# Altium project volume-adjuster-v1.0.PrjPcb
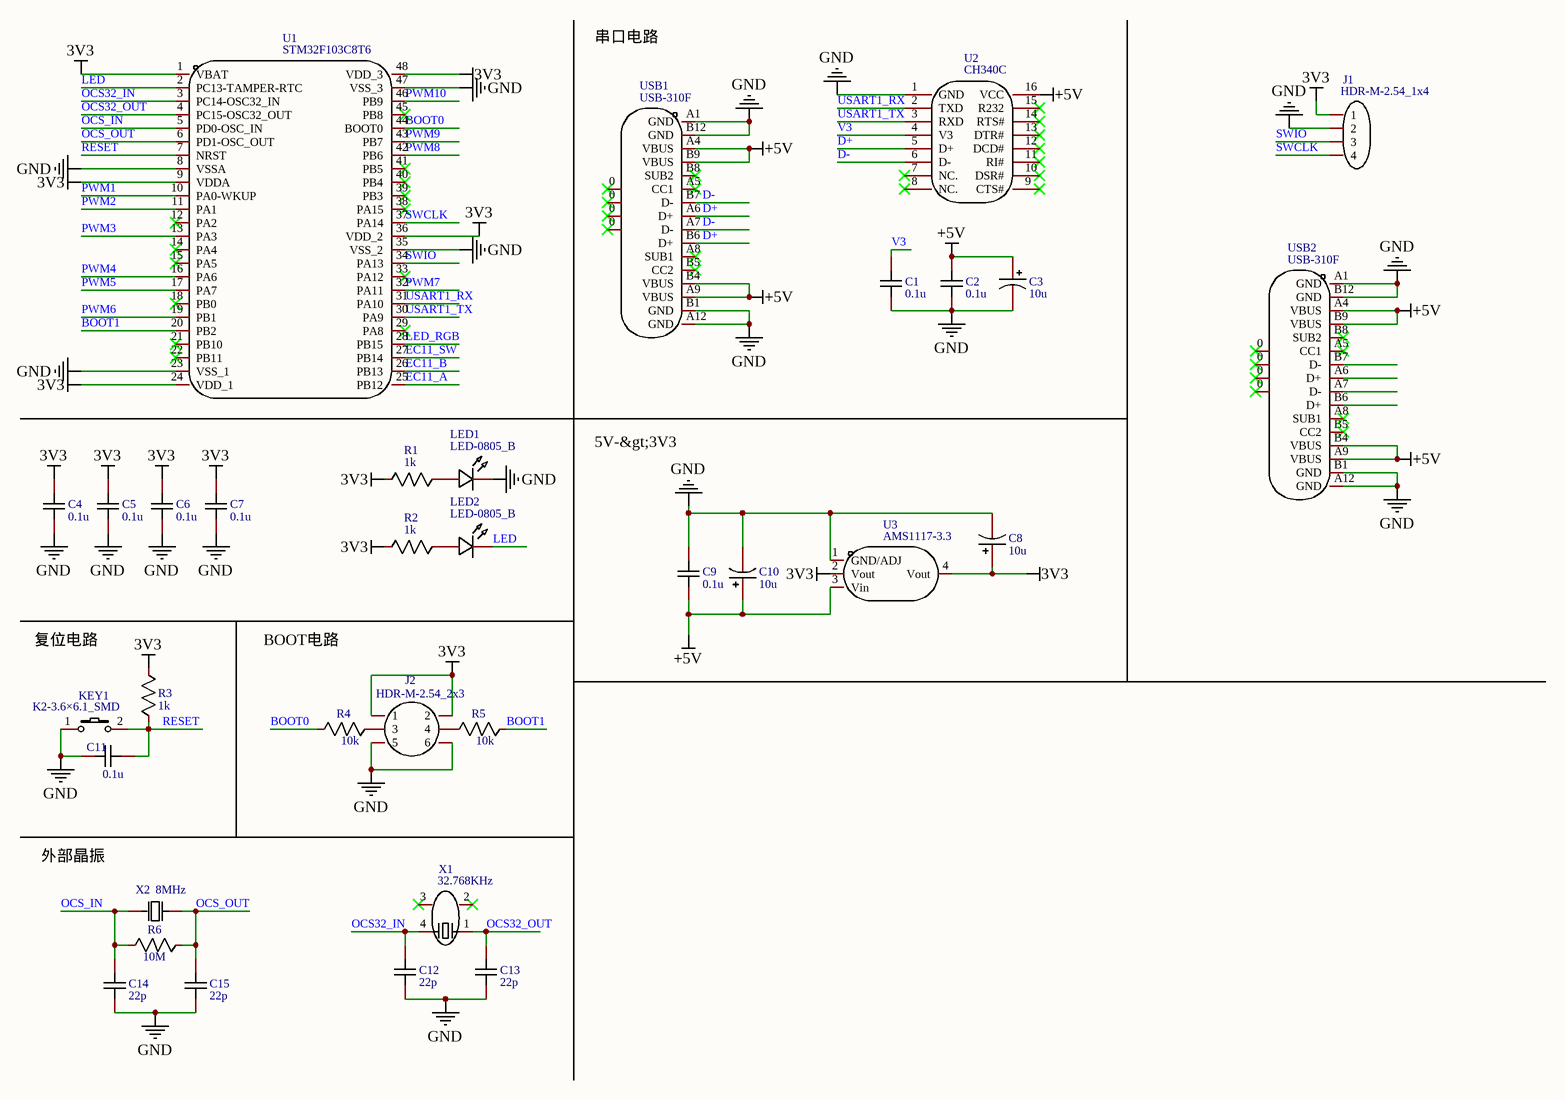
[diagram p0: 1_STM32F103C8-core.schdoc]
2 sheets, 59 parts. Net scope: global (net labels, ports and power ports of the same name join across sheets).
Board file: PCB_volume-adjuster.pcbdoc
Sheets:
  1_STM32F103C8-core.schdoc
  2_外围电路.schdoc

## Sheet 1_STM32F103C8-core.schdoc
size 497 x 243 mm; Name: A_A4; Symbol: A_A4; Device: A_A4; @Project Name: volume-adjuster-v1.0; REV: 1.0; Date: 2023-04-22; Sheet: 1/1; Draw By: wfei &amp; zzc; Company: 眼镜蛇小队; Convert to PCB: yes; Add into BOM: yes; SheetNumber: 1; SheetTotal: 2

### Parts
C1  0.1u  [C0805]
C2  0.1u  [C0805]
C3  10u  [CASE-A_3216]
C4  0.1u  [C0805]
C5  0.1u  [C0805]
C6  0.1u  [C0805]
C7  0.1u  [C0805]
C8  10u  [CASE-A_3216]
C9  0.1u  [C0805]
C10  10u  [CASE-A_3216]
C11  0.1u  [C0805]
C12  22p  [C0805]
C13  22p  [C0805]
C14  22p  [C0805]
C15  22p  [C0805]
J1  HDR-M-2.54_1x4  [HDR-M-2.54_1X4]
J2  HDR-M-2.54_2x3  [HDR-M-2.54_2X3]
KEY1  K2-3.6×6.1_SMD  [KEY-SMD_2P-L6.2-W3.6-LS8.0]
LED1  LED-0805_B  [LED0805_BLUE]
LED2  LED-0805_B  [LED0805_BLUE]
R1  1k  [R0805]
R2  1k  [R0805]
R3  1k  [R0805]
R4  10k  [R0805]
R5  10k  [R0805]
R6  10M  [R0805]
U1  STM32F103C8T6  [LQFP-48_L7.0-W7.0-P0.50-LS9.0-BL]
U2  CH340C  [SOP-16_L10.0-W3.9-P1.27-LS6.0-BL]
U3  AMS1117-3.3  [SOT-223-3_L6.5-W3.4-P2.30-LS7.0-BR]
USB1  USB-310F  [USB-C-SMD_20P-P0.50-L6.5-W8.9]
USB2  USB-310F  [USB-C-SMD_20P-P0.50-L6.5-W8.9]
X1  32.768KHz  [MC-306_4P-L8.0-W3.2-P5.5-BL]
X2  8MHz  [OSC-TH_L11.1-W4.7-P4.88]

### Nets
3V3: C4.2 C5.2 C6.2 C7.2 C8.1 J1.1 J2.1 J2.2 R1.1 R2.1 R3.2 U1.1(VBAT) U1.9(VDDA) U1.24(VDD_1) U1.36(VDD_2) U1.48(VDD_3) U3.2(Vout) U3.4(Vout)
+5V: C2.2 C3.1 C9.1 C10.1 U2.16(VCC) U3.3(Vin) USB1.A4(VBUS) USB1.A9(VBUS) USB1.B4(VBUS) USB1.B9(VBUS) USB2.A4(VBUS) USB2.A9(VBUS) USB2.B4(VBUS) USB2.B9(VBUS)
GND: C1.1 C2.1 C3.2 C4.1 C5.1 C6.1 C7.1 C8.2 C9.2 C10.2 C11.2 C12.1 C13.1 C14.1 C15.1 J1.2 J2.5 J2.6 KEY1.1 LED1.2 U1.8(VSSA) U1.23(VSS_1) U1.35(VSS_2) U1.47(VSS_3) U2.1(GND) U3.1(GND/ADJ) USB1.A1(GND) USB1.A12(GND) USB1.B1(GND) USB1.B12(GND) USB2.A1(GND) USB2.A12(GND) USB2.B1(GND) USB2.B12(GND)
BOOT0: R4.1 U1.44(BOOT0)
BOOT1: R5.2 U1.20(PB2)
D+: U2.5(D+) USB1.A6(D+) USB1.B6(D+)
D-: U2.6(D-) USB1.A7(D-) USB1.B7(D-)
EC11_A: U1.25(PB12)
EC11_B: U1.26(PB13)
EC11_SW: U1.27(PB14)
LED: LED2.2 U1.2(PC13-TAMPER-RTC)
LED_RGB: U1.28(PB15)
OCS32_IN: C12.2 U1.3(PC14-OSC32_IN) X1.4
OCS32_OUT: C13.2 U1.4(PC15-OSC32_OUT) X1.1
OCS_IN: C14.2 R6.1 U1.5(PD0-OSC_IN) X2.1(OSC1)
OCS_OUT: C15.2 R6.2 U1.6(PD1-OSC_OUT) X2.2(OSC2)
PWM1: U1.10(PA0-WKUP)
PWM2: U1.11(PA1)
PWM3: U1.13(PA3)
PWM4: U1.16(PA6)
PWM5: U1.17(PA7)
PWM6: U1.19(PB1)
PWM7: U1.32(PA11)
PWM8: U1.42(PB6)
PWM9: U1.43(PB7)
PWM10: U1.46(PB9)
RESET: C11.1 KEY1.2 R3.1 U1.7(NRST)
SWCLK: J1.4 U1.37(PA14)
SWIO: J1.3 U1.34(PA13)
USART1_RX: U1.31(PA10) U2.2(TXD)
USART1_TX: U1.30(PA9) U2.3(RXD)
V3: C1.2 U2.4(V3)
NetJ2_3: J2.3 R4.2
NetJ2_4: J2.4 R5.1
NetLED1_1: LED1.1 R1.2
NetLED2_1: LED2.1 R2.2

Not connected (* = marked no-connect by the designer): U1 12(PA2)* 14(PA4)* 15(PA5)* 18(PB0)* 21(PB10)* 22(PB11)* 29(PA8)* 33(PA12)* 38(PA15)* 39(PB3)* 40(PB4)* 41(PB5)* 45(PB8)*; U2 7(NC.)* 8(NC.)* 9(CTS#)* 10(DSR#)* 11(RI#)* 12(DCD#)* 13(DTR#)* 14(RTS#)* 15(R232)*; USB1 0* A5(CC1)* A8(SUB1)* B5(CC2)* B8(SUB2)*; USB2 0* A5(CC1)* A6(D+) A7(D-) A8(SUB1)* B5(CC2)* B6(D+) B7(D-) B8(SUB2)*; X1 2* 3*

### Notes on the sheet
- 串口电路
- 5V-&gt;3V3
- 复位电路
- BOOT电路
- 外部晶振

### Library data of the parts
C1 C2 C4-C7 C9 C11 = 0.1u: Convert to PCB: yes
C3 C8 C10 = 10u: Convert to PCB: yes
C12-C15 = 22p: Convert to PCB: yes
J1 = HDR-M-2.54_1x4: Convert to PCB: yes
J2 = HDR-M-2.54_2x3: Convert to PCB: yes
KEY1 = K2-1107ST-A4SW-06: 制造商: 韩国韩荣; Convert to PCB: yes
LED1 LED2 = D-B080508B1-KS2: Manufacturer: 方舟 ARKLED; Convert to PCB: yes
R1-R3 = 1k: Convert to PCB: yes
R4 R5 = 10k: Convert to PCB: yes
R6 = 10M: Convert to PCB: yes
U1 = STM32F103C8T6: Manufacturer: STMicroelectronics; Convert to PCB: yes
U2 = CH340C: Manufacturer: WCH; Convert to PCB: yes
U3 = AMS1117-3.3: Manufacturer: AMS; Convert to PCB: yes
USB1 USB2 = USB-310F: Manufacturer: HOOYA; Convert to PCB: yes
X1 = Q13MC3061000300: Manufacturer: EPSON; Convert to PCB: yes
X2 = S1C80000VWGAC: 频率:8MHz;频率公差:±20ppm;频率稳定度:±30ppm;负载电容:16pF;; Manufacturer: JYJE(晶友嘉); Add into BOM: yes; Crystal Type: 直插无源晶振; Frequency Tolerance: ±20ppm; Frequency Stability: ±30ppm; Load Capacitance: 16pF; Equivalent Series Resistance (ESR): 60Ω

## Sheet 2_外围电路.schdoc
size 497 x 243 mm; Name: A_A4; Symbol: A_A4; Device: A_A4; @Project Name: volume-adjuster-v1.0; REV: 1.0; Date: 2023-04-22; Sheet: 1/1; Draw By: wfei &amp; zzc; Company: Your Company; Convert to PCB: yes; Add into BOM: yes; SheetNumber: 2; SheetTotal: 2
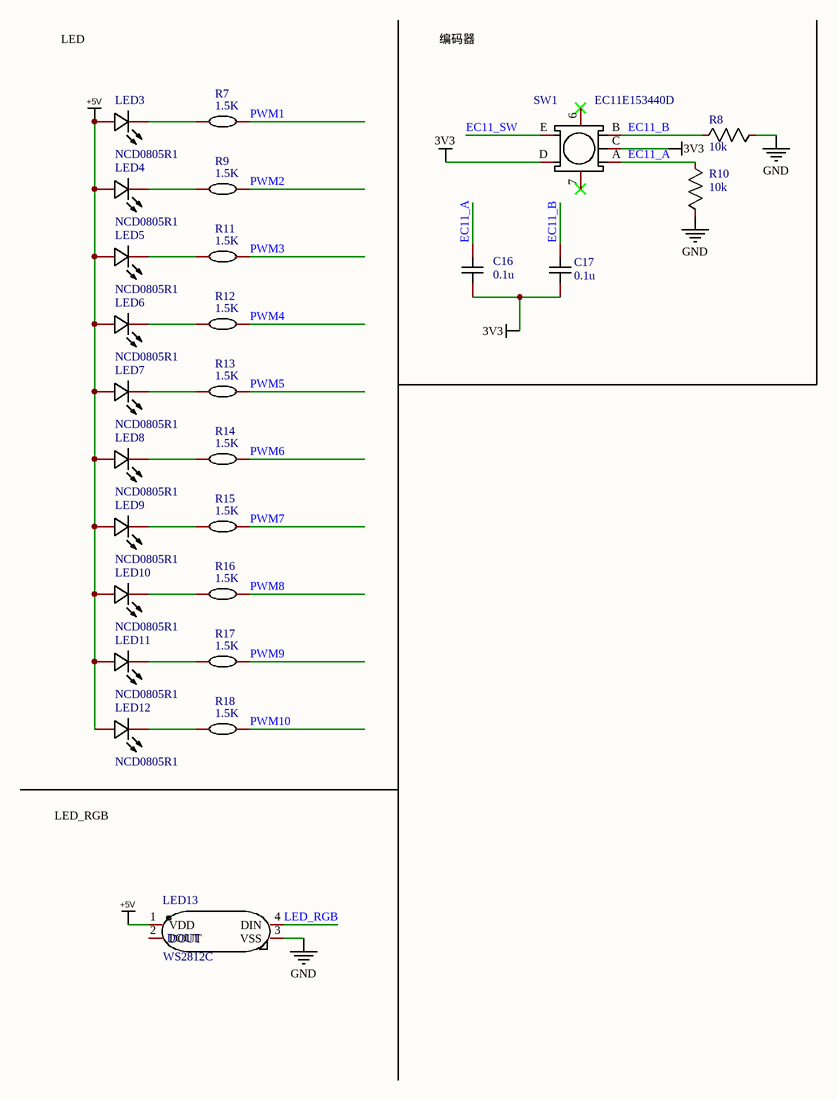
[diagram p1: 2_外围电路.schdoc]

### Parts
C16  0.1u  [C0805]
C17  0.1u  [C0805]
LED3  NCD0805R1  [LED0805-RD_RED]
LED4  NCD0805R1  [LED0805-RD_RED]
LED5  NCD0805R1  [LED0805-RD_RED]
LED6  NCD0805R1  [LED0805-RD_RED]
LED7  NCD0805R1  [LED0805-RD_RED]
LED8  NCD0805R1  [LED0805-RD_RED]
LED9  NCD0805R1  [LED0805-RD_RED]
LED10  NCD0805R1  [LED0805-RD_RED]
LED11  NCD0805R1  [LED0805-RD_RED]
LED12  NCD0805R1  [LED0805-RD_RED]
LED13  NAME: DOUT  [LED-SMD_4P-L5.0-W5.0-LS5.4-TL-1]  (hidden comment: WS2812C)
R7  1.5K  [R0805]
R8  10k  [R0805]
R9  1.5K  [R0805]
R10  10k  [R0805]
R11  1.5K  [R0805]
R12  1.5K  [R0805]
R13  1.5K  [R0805]
R14  1.5K  [R0805]
R15  1.5K  [R0805]
R16  1.5K  [R0805]
R17  1.5K  [R0805]
R18  1.5K  [R0805]
SW1  EC11E153440D  [SW-TH_EC11XXXXXXXX]

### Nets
3V3: C16.1 C17.1 SW1.C SW1.D
+5V: LED3.2(+) LED4.2(+) LED5.2(+) LED6.2(+) LED7.2(+) LED8.2(+) LED9.2(+) LED10.2(+) LED11.2(+) LED12.2(+) LED13.1(VDD)
GND: LED13.3(VSS) R8.1 R10.2
EC11_A: C16.2 R10.1 SW1.A
EC11_B: C17.2 R8.2 SW1.B
EC11_SW: SW1.E
LED_RGB: LED13.4(DIN)
PWM1: R7.2
PWM2: R9.2
PWM3: R11.2
PWM4: R12.2
PWM5: R13.2
PWM6: R14.2
PWM7: R15.2
PWM8: R16.2
PWM9: R17.2
PWM10: R18.2
NetLED3_1: LED3.1(-) R7.1
NetLED4_1: LED4.1(-) R9.1
NetLED5_1: LED5.1(-) R11.1
NetLED6_1: LED6.1(-) R12.1
NetLED7_1: LED7.1(-) R13.1
NetLED8_1: LED8.1(-) R14.1
NetLED9_1: LED9.1(-) R15.1
NetLED10_1: LED10.1(-) R16.1
NetLED11_1: LED11.1(-) R17.1
NetLED12_1: LED12.1(-) R18.1

Not connected (* = marked no-connect by the designer): LED13 2(DOUT); SW1 6* 7*

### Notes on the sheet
- LED
- 编码器
- LED_RGB

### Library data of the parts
C16 C17 = 0.1u: Convert to PCB: yes
LED3-LED12 = NCD0805R1: 发光颜色:红灯;; Manufacturer: 国星光电; Symbol: FC-2012HRK-620D; Add into BOM: yes; Emitted Color: 红灯
LED13 = WS2812C: 发光颜色:RGB三色;; Manufacturer: worldsemi; Add into BOM: yes; Emitted Color: RGB三色
R7 R9 R11-R18 = AC0805FR-071K5L: Manufacturer: YAGEO(国巨); Resistance: 1.5kΩ; Convert to PCB: yes
R8 R10 = 10k: Convert to PCB: yes
SW1 = EC11E153440D: Manufacturer: ALPSALPINE(阿尔卑斯阿尔派); Add into BOM: yes

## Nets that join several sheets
3V3: 1_STM32F103C8-core (18 pins), 2_外围电路 (C16.1 C17.1 SW1.C SW1.D)
+5V: 1_STM32F103C8-core (14 pins), 2_外围电路 (11 pins)
GND: 1_STM32F103C8-core (34 pins), 2_外围电路 (LED13.3 R8.1 R10.2)
EC11_A: 1_STM32F103C8-core (U1.25), 2_外围电路 (C16.2 R10.1 SW1.A)
EC11_B: 1_STM32F103C8-core (U1.26), 2_外围电路 (C17.2 R8.2 SW1.B)
EC11_SW: 1_STM32F103C8-core (U1.27), 2_外围电路 (SW1.E)
LED_RGB: 1_STM32F103C8-core (U1.28), 2_外围电路 (LED13.4)
PWM1: 1_STM32F103C8-core (U1.10), 2_外围电路 (R7.2)
PWM2: 1_STM32F103C8-core (U1.11), 2_外围电路 (R9.2)
PWM3: 1_STM32F103C8-core (U1.13), 2_外围电路 (R11.2)
PWM4: 1_STM32F103C8-core (U1.16), 2_外围电路 (R12.2)
PWM5: 1_STM32F103C8-core (U1.17), 2_外围电路 (R13.2)
PWM6: 1_STM32F103C8-core (U1.19), 2_外围电路 (R14.2)
PWM7: 1_STM32F103C8-core (U1.32), 2_外围电路 (R15.2)
PWM8: 1_STM32F103C8-core (U1.42), 2_外围电路 (R16.2)
PWM9: 1_STM32F103C8-core (U1.43), 2_外围电路 (R17.2)
PWM10: 1_STM32F103C8-core (U1.46), 2_外围电路 (R18.2)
